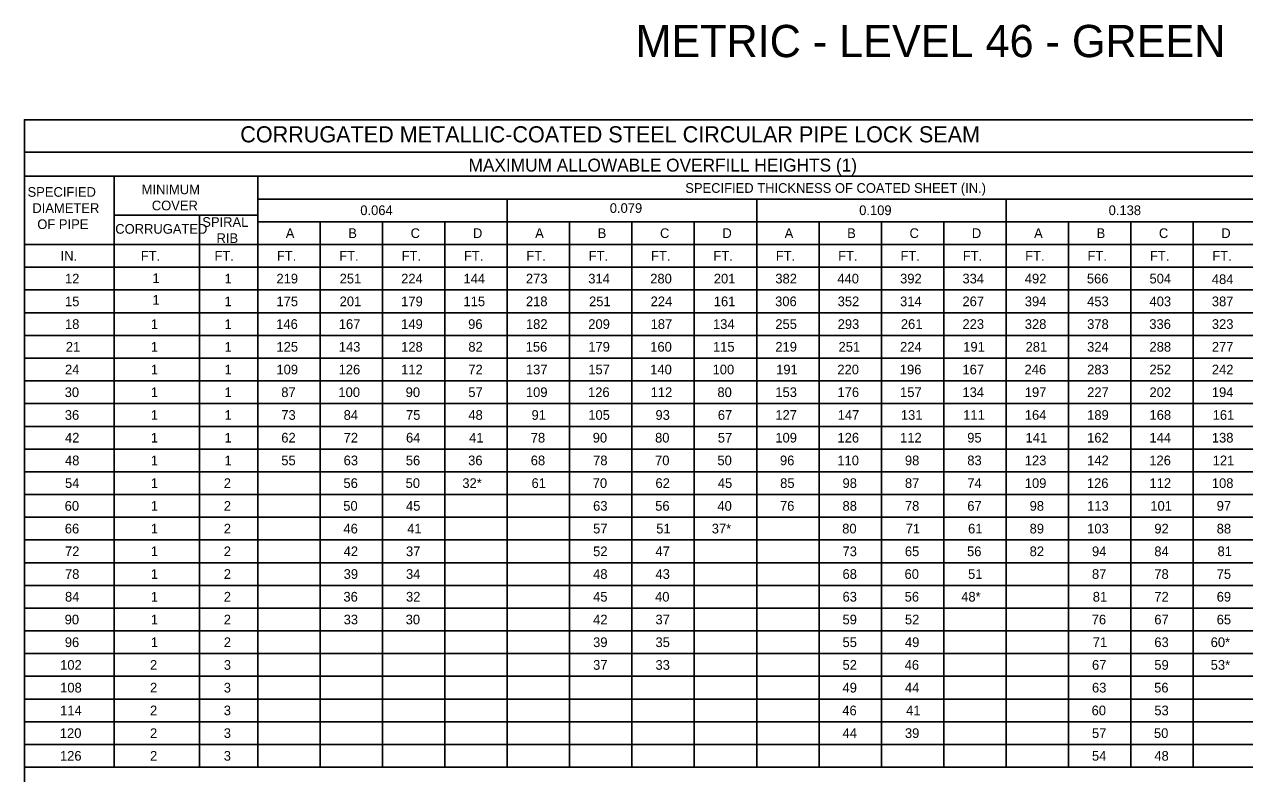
# Model space of a CAD drawing. Extents: x -439.1 to -407.9, y -458.1 to -436.2.
# Drawn here: x -439.11 to -420.2, y -447.81 to -436.2 of the extents above; entities that cross this region are included whole.
import ezdxf

# ---------------------------------------------------------------- set-up
doc = ezdxf.new("R2010")
doc.units = 0
for name, color, linetype in [('Draft_Named_Boundary', 7, 'Continuous'), ('Level 4', 7, 'Continuous'), ('Level 46', 7, 'Continuous')]:
    doc.layers.add(name, color=color, linetype=linetype)

msp = doc.modelspace()

# ---------------------------------------------------------------- linework, layer by layer
at = {"layer": 'Draft_Named_Boundary'}
msp.add_lwpolyline([(-439.109, -458.051), (-407.859, -458.051), (-407.859, -437.676), (-439.109, -437.676)], close=True, dxfattribs=at)
at = {"layer": 'Level 4'}
for p, q in [((-439.109, -437.676), (-416.17, -437.676)), ((-439.109, -447.71), (-439.109, -437.676)), ((-439.109, -438.177), (-416.17, -438.177)), ((-439.109, -438.552), (-416.17, -438.552)), ((-437.72, -447.71), (-437.72, -438.552)), ((-435.493, -447.71), (-435.493, -438.552)), ((-435.493, -438.905), (-416.17, -438.905)), ((-431.629, -447.71), (-431.629, -438.905)), ((-427.764, -447.71), (-427.764, -438.905)), ((-423.9, -447.71), (-423.9, -438.905)), ((-437.72, -439.154), (-435.493, -439.154)), ((-436.396, -447.71), (-436.396, -439.154)), ((-435.493, -439.257), (-416.17, -439.257)), ((-434.527, -447.71), (-434.527, -439.257)), ((-433.561, -447.71), (-433.561, -439.257)), ((-432.595, -447.71), (-432.595, -439.257)), ((-430.663, -447.71), (-430.663, -439.257)), ((-429.696, -447.71), (-429.696, -439.257)), ((-428.73, -447.71), (-428.73, -439.257)), ((-426.798, -447.71), (-426.798, -439.257)), ((-425.832, -447.71), (-425.832, -439.257)), ((-424.866, -447.71), (-424.866, -439.257)), ((-422.933, -447.71), (-422.933, -439.257)), ((-421.967, -447.71), (-421.967, -439.257)), ((-421.001, -447.71), (-421.001, -439.257)), ((-439.109, -439.609), (-416.17, -439.609)), ((-439.109, -439.961), (-416.17, -439.961)), ((-439.109, -440.313), (-416.17, -440.313)), ((-439.109, -440.666), (-416.17, -440.666)), ((-439.109, -441.018), (-416.17, -441.018)), ((-439.109, -441.37), (-416.17, -441.37)), ((-439.109, -441.722), (-416.17, -441.722)), ((-439.109, -442.075), (-416.17, -442.075)), ((-439.109, -442.427), (-416.17, -442.427)), ((-439.109, -442.779), (-416.17, -442.779)), ((-439.109, -443.131), (-416.17, -443.131)), ((-439.109, -443.483), (-416.17, -443.483)), ((-439.109, -443.836), (-416.17, -443.836)), ((-439.109, -444.188), (-416.17, -444.188)), ((-439.109, -444.54), (-416.17, -444.54)), ((-439.109, -444.892), (-416.17, -444.892)), ((-439.109, -445.245), (-416.17, -445.245)), ((-439.109, -445.597), (-416.17, -445.597)), ((-439.109, -445.949), (-416.17, -445.949)), ((-439.109, -446.301), (-416.17, -446.301)), ((-439.109, -446.654), (-416.17, -446.654)), ((-439.109, -447.006), (-416.17, -447.006)), ((-439.109, -447.358), (-416.17, -447.358)), ((-439.109, -447.71), (-416.17, -447.71))]:
    msp.add_line(p, q, dxfattribs=at)

# ---------------------------------------------------------------- texts
for s, height, p in [('CORRUGATED METALLIC-COATED STEEL CIRCULAR PIPE LOCK SEAM', 0.25, (-435.765, -438.026)), ('MAXIMUM ALLOWABLE OVERFILL HEIGHTS (1)', 0.2, (-432.228, -438.478)), ('SPECIFIED', 0.15, (-439.06, -438.869)), ('MINIMUM', 0.15, (-437.292, -438.829)), ('SPECIFIED THICKNESS OF COATED SHEET (IN.)', 0.15, (-428.87, -438.808)), ('COVER', 0.15, (-437.135, -439.079)), ('DIAMETER', 0.15, (-438.985, -439.119)), ('0.064', 0.15, (-433.905, -439.153)), ('0.079', 0.15, (-430.04, -439.119)), ('0.109', 0.15, (-426.176, -439.153)), ('0.138', 0.15, (-422.311, -439.153)), ('OF PIPE', 0.15, (-438.909, -439.369)), ('CORRUGATED', 0.15, (-437.701, -439.442)), ('SPIRAL', 0.15, (-436.353, -439.335)), ('RIB', 0.15, (-436.132, -439.585)), ('A', 0.15, (-435.06, -439.508)), ('B', 0.15, (-434.091, -439.508)), ('C', 0.15, (-433.125, -439.508)), ('D', 0.15, (-432.159, -439.508)), ('A', 0.15, (-431.196, -439.508)), ('B', 0.15, (-430.227, -439.508)), ('C', 0.15, (-429.261, -439.508)), ('D', 0.15, (-428.295, -439.508)), ('A', 0.15, (-427.331, -439.508)), ('B', 0.15, (-426.362, -439.508)), ('C', 0.15, (-425.396, -439.508)), ('D', 0.15, (-424.43, -439.508)), ('A', 0.15, (-423.466, -439.508)), ('B', 0.15, (-422.498, -439.508)), ('C', 0.15, (-421.532, -439.508)), ('D', 0.15, (-420.566, -439.508)), ('IN.', 0.15, (-438.548, -439.86)), ('FT.', 0.15, (-437.306, -439.86)), ('FT.', 0.15, (-436.164, -439.86)), ('FT.', 0.15, (-435.197, -439.86)), ('FT.', 0.15, (-434.231, -439.86)), ('FT.', 0.15, (-433.265, -439.86)), ('FT.', 0.15, (-432.299, -439.86)), ('FT.', 0.15, (-431.333, -439.86)), ('FT.', 0.15, (-430.367, -439.86)), ('FT.', 0.15, (-429.401, -439.86)), ('FT.', 0.15, (-428.434, -439.86)), ('FT.', 0.15, (-427.468, -439.86)), ('FT.', 0.15, (-426.502, -439.86)), ('FT.', 0.15, (-425.536, -439.86)), ('FT.', 0.15, (-424.57, -439.86)), ('FT.', 0.15, (-423.604, -439.86)), ('FT.', 0.15, (-422.638, -439.86)), ('FT.', 0.15, (-421.671, -439.86)), ('FT.', 0.15, (-420.705, -439.86)), ('12', 0.15, (-438.48, -440.212)), ('1', 0.15, (-437.125, -440.205)), ('1', 0.15, (-436.008, -440.212)), ('219', 0.15, (-435.204, -440.212)), ('251', 0.15, (-434.225, -440.212)), ('224', 0.15, (-433.272, -440.212)), ('144', 0.15, (-432.306, -440.212)), ('273', 0.15, (-431.339, -440.212)), ('314', 0.15, (-430.373, -440.212)), ('280', 0.15, (-429.413, -440.212)), ('201', 0.15, (-428.428, -440.212)), ('382', 0.15, (-427.475, -440.212)), ('440', 0.15, (-426.514, -440.212)), ('392', 0.15, (-425.542, -440.212)), ('334', 0.15, (-424.576, -440.212)), ('492', 0.15, (-423.61, -440.212)), ('566', 0.15, (-422.648, -440.212)), ('504', 0.15, (-421.678, -440.212)), ('484', 0.15, (-420.712, -440.221)), ('15', 0.15, (-438.48, -440.565)), ('1', 0.15, (-437.125, -440.541)), ('1', 0.15, (-436.008, -440.565)), ('175', 0.15, (-435.204, -440.565)), ('201', 0.15, (-434.225, -440.565)), ('179', 0.15, (-433.272, -440.565)), ('115', 0.15, (-432.306, -440.565)), ('218', 0.15, (-431.339, -440.565)), ('251', 0.15, (-430.361, -440.565)), ('224', 0.15, (-429.407, -440.565)), ('161', 0.15, (-428.428, -440.565)), ('306', 0.15, (-427.478, -440.565)), ('352', 0.15, (-426.509, -440.565)), ('314', 0.15, (-425.542, -440.565)), ('267', 0.15, (-424.576, -440.565)), ('394', 0.15, (-423.61, -440.565)), ('453', 0.15, (-422.644, -440.565)), ('403', 0.15, (-421.678, -440.565)), ('387', 0.15, (-420.712, -440.565)), ('18', 0.15, (-438.48, -440.917)), ('1', 0.15, (-437.15, -440.917)), ('1', 0.15, (-436.008, -440.917)), ('146', 0.15, (-435.208, -440.917)), ('167', 0.15, (-434.238, -440.917)), ('149', 0.15, (-433.272, -440.917)), ('96', 0.15, (-432.234, -440.917)), ('182', 0.15, (-431.339, -440.917)), ('209', 0.15, (-430.373, -440.917)), ('187', 0.15, (-429.407, -440.917)), ('134', 0.15, (-428.441, -440.917)), ('255', 0.15, (-427.475, -440.917)), ('293', 0.15, (-426.509, -440.917)), ('261', 0.15, (-425.53, -440.917)), ('223', 0.15, (-424.576, -440.917)), ('328', 0.15, (-423.61, -440.917)), ('378', 0.15, (-422.644, -440.917)), ('336', 0.15, (-421.681, -440.917)), ('323', 0.15, (-420.712, -440.917)), ('21', 0.15, (-438.467, -441.269)), ('1', 0.15, (-437.15, -441.269)), ('1', 0.15, (-436.008, -441.269)), ('125', 0.15, (-435.204, -441.269)), ('143', 0.15, (-434.238, -441.269)), ('128', 0.15, (-433.272, -441.269)), ('82', 0.15, (-432.231, -441.269)), ('156', 0.15, (-431.343, -441.269)), ('179', 0.15, (-430.373, -441.269)), ('160', 0.15, (-429.413, -441.269)), ('115', 0.15, (-428.441, -441.269)), ('219', 0.15, (-427.475, -441.269)), ('251', 0.15, (-426.496, -441.269)), ('224', 0.15, (-425.542, -441.269)), ('191', 0.15, (-424.564, -441.269)), ('281', 0.15, (-423.598, -441.269)), ('324', 0.15, (-422.644, -441.269)), ('288', 0.15, (-421.678, -441.269)), ('277', 0.15, (-420.712, -441.269)), ('24', 0.15, (-438.48, -441.621)), ('1', 0.15, (-437.15, -441.621)), ('1', 0.15, (-436.008, -441.621)), ('109', 0.15, (-435.204, -441.621)), ('126', 0.15, (-434.241, -441.621)), ('112', 0.15, (-433.272, -441.621)), ('72', 0.15, (-432.231, -441.621)), ('137', 0.15, (-431.339, -441.621)), ('157', 0.15, (-430.373, -441.621)), ('140', 0.15, (-429.413, -441.621)), ('100', 0.15, (-428.447, -441.621)), ('191', 0.15, (-427.462, -441.621)), ('220', 0.15, (-426.514, -441.621)), ('196', 0.15, (-425.546, -441.621)), ('167', 0.15, (-424.576, -441.621)), ('246', 0.15, (-423.614, -441.621)), ('283', 0.15, (-422.644, -441.621)), ('252', 0.15, (-421.678, -441.621)), ('242', 0.15, (-420.712, -441.621)), ('30', 0.15, (-438.485, -441.973)), ('1', 0.15, (-437.15, -441.973)), ('1', 0.15, (-436.008, -441.973)), ('87', 0.15, (-435.129, -441.973)), ('100', 0.15, (-434.244, -441.973)), ('90', 0.15, (-433.202, -441.973)), ('57', 0.15, (-432.231, -441.973)), ('109', 0.15, (-431.339, -441.973)), ('126', 0.15, (-430.377, -441.973)), ('112', 0.15, (-429.407, -441.973)), ('80', 0.15, (-428.372, -441.973)), ('153', 0.15, (-427.475, -441.973)), ('176', 0.15, (-426.512, -441.973)), ('157', 0.15, (-425.542, -441.973)), ('134', 0.15, (-424.576, -441.973)), ('197', 0.15, (-423.61, -441.973)), ('227', 0.15, (-422.644, -441.973)), ('202', 0.15, (-421.678, -441.973)), ('194', 0.15, (-420.712, -441.973)), ('36', 0.15, (-438.483, -442.326)), ('1', 0.15, (-437.15, -442.326)), ('1', 0.15, (-436.008, -442.326)), ('73', 0.15, (-435.129, -442.326)), ('84', 0.15, (-434.163, -442.326)), ('75', 0.15, (-433.197, -442.326)), ('48', 0.15, (-432.231, -442.326)), ('91', 0.15, (-431.252, -442.326)), ('105', 0.15, (-430.373, -442.326)), ('93', 0.15, (-429.332, -442.326)), ('67', 0.15, (-428.366, -442.326)), ('127', 0.15, (-427.475, -442.326)), ('147', 0.15, (-426.509, -442.326)), ('131', 0.15, (-425.53, -442.326)), ('111', 0.15, (-424.564, -442.326)), ('164', 0.15, (-423.61, -442.326)), ('189', 0.15, (-422.644, -442.326)), ('168', 0.15, (-421.678, -442.326)), ('161', 0.15, (-420.699, -442.326)), ('42', 0.15, (-438.48, -442.678)), ('1', 0.15, (-437.15, -442.678)), ('1', 0.15, (-436.008, -442.678)), ('62', 0.15, (-435.129, -442.678)), ('72', 0.15, (-434.163, -442.678)), ('64', 0.15, (-433.197, -442.678)), ('41', 0.15, (-432.218, -442.678)), ('78', 0.15, (-431.264, -442.678)), ('90', 0.15, (-430.304, -442.678)), ('80', 0.15, (-429.338, -442.678)), ('57', 0.15, (-428.366, -442.678)), ('109', 0.15, (-427.475, -442.678)), ('126', 0.15, (-426.512, -442.678)), ('112', 0.15, (-425.542, -442.678)), ('95', 0.15, (-424.502, -442.678)), ('141', 0.15, (-423.598, -442.678)), ('162', 0.15, (-422.644, -442.678)), ('144', 0.15, (-421.678, -442.678)), ('138', 0.15, (-420.712, -442.678)), ('48', 0.15, (-438.48, -443.03)), ('1', 0.15, (-437.15, -443.03)), ('1', 0.15, (-436.008, -443.03)), ('55', 0.15, (-435.129, -443.03)), ('63', 0.15, (-434.163, -443.03)), ('56', 0.15, (-433.2, -443.03)), ('36', 0.15, (-432.234, -443.03)), ('68', 0.15, (-431.264, -443.03)), ('78', 0.15, (-430.298, -443.03)), ('70', 0.15, (-429.338, -443.03)), ('50', 0.15, (-428.372, -443.03)), ('96', 0.15, (-427.403, -443.03)), ('110', 0.15, (-426.514, -443.03)), ('98', 0.15, (-425.467, -443.03)), ('83', 0.15, (-424.501, -443.03)), ('123', 0.15, (-423.61, -443.03)), ('142', 0.15, (-422.644, -443.03)), ('126', 0.15, (-421.681, -443.03)), ('121', 0.15, (-420.699, -443.03)), ('54', 0.15, (-438.48, -443.382)), ('1', 0.15, (-437.15, -443.382)), ('2', 0.15, (-436.02, -443.382)), ('56', 0.15, (-434.166, -443.382)), ('50', 0.15, (-433.203, -443.382)), ('32*', 0.15, (-432.324, -443.382)), ('61', 0.15, (-431.252, -443.382)), ('70', 0.15, (-430.304, -443.382)), ('62', 0.15, (-429.332, -443.382)), ('45', 0.15, (-428.366, -443.382)), ('85', 0.15, (-427.4, -443.382)), ('98', 0.15, (-426.434, -443.382)), ('87', 0.15, (-425.467, -443.382)), ('74', 0.15, (-424.501, -443.382)), ('109', 0.15, (-423.61, -443.382)), ('126', 0.15, (-422.648, -443.382)), ('112', 0.15, (-421.678, -443.382)), ('108', 0.15, (-420.712, -443.382)), ('60', 0.15, (-438.485, -443.735)), ('1', 0.15, (-437.15, -443.735)), ('2', 0.15, (-436.02, -443.735)), ('50', 0.15, (-434.169, -443.735)), ('45', 0.15, (-433.197, -443.735)), ('63', 0.15, (-430.298, -443.735)), ('56', 0.15, (-429.336, -443.735)), ('40', 0.15, (-428.372, -443.735)), ('76', 0.15, (-427.403, -443.735)), ('88', 0.15, (-426.434, -443.735)), ('78', 0.15, (-425.467, -443.735)), ('67', 0.15, (-424.501, -443.735)), ('98', 0.15, (-423.535, -443.735)), ('113', 0.15, (-422.644, -443.735)), ('101', 0.15, (-421.665, -443.735)), ('97', 0.15, (-420.637, -443.735)), ('66', 0.15, (-438.483, -444.087)), ('1', 0.15, (-437.15, -444.087)), ('2', 0.15, (-436.02, -444.087)), ('46', 0.15, (-434.166, -444.087)), ('41', 0.15, (-433.178, -444.087)), ('57', 0.15, (-430.298, -444.087)), ('51', 0.15, (-429.32, -444.087)), ('37*', 0.15, (-428.46, -444.087)), ('80', 0.15, (-426.439, -444.087)), ('71', 0.15, (-425.455, -444.087)), ('61', 0.15, (-424.489, -444.087)), ('89', 0.15, (-423.535, -444.087)), ('103', 0.15, (-422.644, -444.087)), ('92', 0.15, (-421.603, -444.087)), ('88', 0.15, (-420.637, -444.087)), ('72', 0.15, (-438.48, -444.439)), ('1', 0.15, (-437.15, -444.439)), ('2', 0.15, (-436.02, -444.439)), ('42', 0.15, (-434.163, -444.439)), ('37', 0.15, (-433.197, -444.439)), ('52', 0.15, (-430.298, -444.439)), ('47', 0.15, (-429.332, -444.439)), ('73', 0.15, (-426.434, -444.439)), ('65', 0.15, (-425.468, -444.439)), ('56', 0.15, (-424.505, -444.439)), ('82', 0.15, (-423.535, -444.439)), ('94', 0.15, (-422.569, -444.439)), ('84', 0.15, (-421.603, -444.439)), ('81', 0.15, (-420.624, -444.439)), ('78', 0.15, (-438.48, -444.791)), ('1', 0.15, (-437.15, -444.791)), ('2', 0.15, (-436.02, -444.791)), ('39', 0.15, (-434.163, -444.791)), ('34', 0.15, (-433.197, -444.791)), ('48', 0.15, (-430.298, -444.791)), ('43', 0.15, (-429.332, -444.791)), ('68', 0.15, (-426.434, -444.791)), ('60', 0.15, (-425.473, -444.791)), ('51', 0.15, (-424.489, -444.791)), ('87', 0.15, (-422.569, -444.791)), ('78', 0.15, (-421.603, -444.791)), ('75', 0.15, (-420.637, -444.791)), ('84', 0.15, (-438.48, -445.143)), ('1', 0.15, (-437.15, -445.143)), ('2', 0.15, (-436.02, -445.143)), ('36', 0.15, (-434.166, -445.143)), ('32', 0.15, (-433.197, -445.143)), ('45', 0.15, (-430.298, -445.143)), ('40', 0.15, (-429.338, -445.143)), ('63', 0.15, (-426.434, -445.143)), ('56', 0.15, (-425.471, -445.143)), ('48*', 0.15, (-424.595, -445.143)), ('81', 0.15, (-422.557, -445.143)), ('72', 0.15, (-421.603, -445.143)), ('69', 0.15, (-420.637, -445.143)), ('90', 0.15, (-438.485, -445.496)), ('1', 0.15, (-437.15, -445.496)), ('2', 0.15, (-436.02, -445.496)), ('33', 0.15, (-434.163, -445.496)), ('30', 0.15, (-433.202, -445.496)), ('42', 0.15, (-430.298, -445.496)), ('37', 0.15, (-429.332, -445.496)), ('59', 0.15, (-426.434, -445.496)), ('52', 0.15, (-425.467, -445.496)), ('76', 0.15, (-422.573, -445.496)), ('67', 0.15, (-421.603, -445.496)), ('65', 0.15, (-420.637, -445.496)), ('96', 0.15, (-438.483, -445.848)), ('1', 0.15, (-437.15, -445.848)), ('2', 0.15, (-436.02, -445.848)), ('39', 0.15, (-430.298, -445.848)), ('35', 0.15, (-429.332, -445.848)), ('55', 0.15, (-426.434, -445.848)), ('49', 0.15, (-425.467, -445.848)), ('71', 0.15, (-422.557, -445.848)), ('63', 0.15, (-421.603, -445.848)), ('60*', 0.15, (-420.73, -445.848)), ('102', 0.15, (-438.555, -446.2)), ('2', 0.15, (-437.163, -446.2)), ('3', 0.15, (-436.02, -446.2)), ('37', 0.15, (-430.298, -446.2)), ('33', 0.15, (-429.332, -446.2)), ('52', 0.15, (-426.434, -446.2)), ('46', 0.15, (-425.471, -446.2)), ('67', 0.15, (-422.569, -446.2)), ('59', 0.15, (-421.603, -446.2)), ('53*', 0.15, (-420.73, -446.2)), ('108', 0.15, (-438.555, -446.552)), ('2', 0.15, (-437.163, -446.552)), ('3', 0.15, (-436.02, -446.552)), ('49', 0.15, (-426.434, -446.552)), ('44', 0.15, (-425.467, -446.552)), ('63', 0.15, (-422.569, -446.552)), ('56', 0.15, (-421.606, -446.552)), ('114', 0.15, (-438.555, -446.905)), ('2', 0.15, (-437.163, -446.905)), ('3', 0.15, (-436.02, -446.905)), ('46', 0.15, (-426.437, -446.905)), ('41', 0.15, (-425.449, -446.905)), ('60', 0.15, (-422.575, -446.905)), ('53', 0.15, (-421.603, -446.905)), ('120', 0.15, (-438.56, -447.257)), ('2', 0.15, (-437.163, -447.257)), ('3', 0.15, (-436.02, -447.257)), ('44', 0.15, (-426.434, -447.257)), ('39', 0.15, (-425.467, -447.257)), ('57', 0.15, (-422.569, -447.257)), ('50', 0.15, (-421.609, -447.257)), ('126', 0.15, (-438.558, -447.609)), ('2', 0.15, (-437.163, -447.609)), ('3', 0.15, (-436.02, -447.609)), ('54', 0.15, (-422.569, -447.609)), ('48', 0.15, (-421.603, -447.609))]:
    msp.add_text(s, height=height, dxfattribs=at).set_placement(p)
at = {"layer": 'Level 46'}
msp.add_text('METRIC - LEVEL 46 - GREEN', height=0.5, dxfattribs=at).set_placement((-429.642, -436.705))

doc.saveas('drawing.dxf')
